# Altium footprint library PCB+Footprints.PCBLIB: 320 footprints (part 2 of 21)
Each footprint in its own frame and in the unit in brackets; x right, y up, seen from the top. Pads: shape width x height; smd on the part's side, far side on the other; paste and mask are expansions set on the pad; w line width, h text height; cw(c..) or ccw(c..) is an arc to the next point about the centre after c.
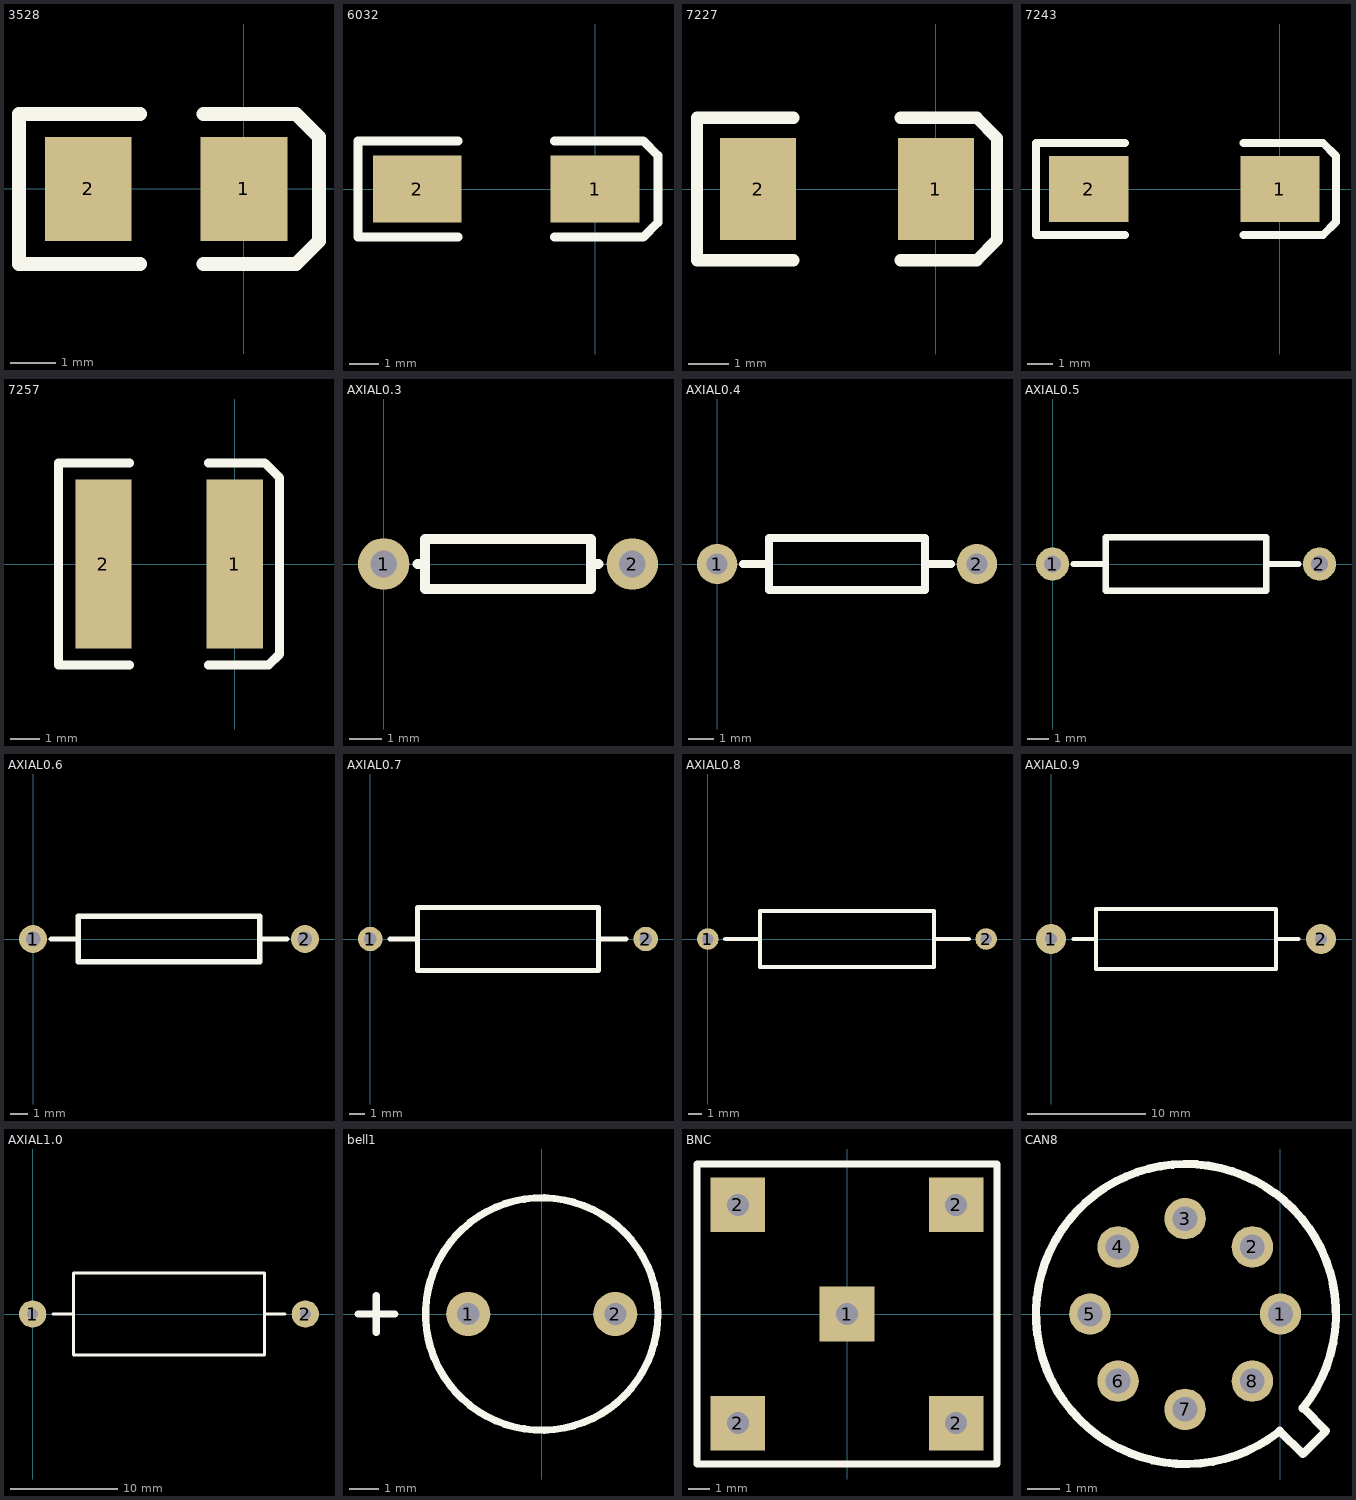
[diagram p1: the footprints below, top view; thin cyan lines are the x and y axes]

## 3528 [mil]
pads (2):
  rect 75x90 smd: 1(0,0) 2(-135,0)
TopOverlay:
  lines w12: -90,-65 -195,-65 -195,65 -90,65 ; -35,-65 45,-65 65,-45 65,45 45,65 -35,65

## 6032 [mil]
pads (2):
  rect 120x90 smd: 1(0,0) 2(-240,0)
TopOverlay:
  lines w12: -185,-65 -320,-65 -320,65 -185,65 ; -55,-65 65,-65 85,-45 85,45 65,65 -55,65

## 7227 [mil]
pads (2):
  rect 75x100 smd: 1(0,0) 2(-175,0)
TopOverlay:
  lines w12: -140,-70 -235,-70 -235,70 -140,70 ; -35,-70 40,-70 60,-50 60,50 40,70 -35,70

## 7243 [mil]
pads (2):
  rect 120x100 smd: 1(0,0) 2(-290,0)
TopOverlay:
  lines w12: -235,-70 -370,-70 -370,70 -235,70 ; -55,-70 65,-70 85,-50 85,50 65,70 -55,70

## 7257 [mil]
pads (2):
  rect 75x225 smd: 1(0,0) 2(-175,0)
TopOverlay:
  lines w12: -140,-135 -235,-135 -235,135 -140,135 ; -35,-135 45,-135 60,-120 60,115 40,135 -35,135

## AXIAL0.3 [mil]
pads (2):
  round 62 hole 32: 1(0,0) 2(300,0)
TopOverlay:
  lines w12: 41,0 50,0 ; 259,0 250,0 ; 250,0 250,-30 50,-30 50,30 250,30 250,0

## AXIAL0.4 [mil]
pads (2):
  round 62 hole 32: 1(0,0) 2(400,0)
TopOverlay:
  lines w12: 40,0 80,0 ; 320,0 360,0 ; 80,-40 80,40 320,40 320,-40 80,-40

## AXIAL0.5 [mil]
pads (2):
  round 62 hole 32: 1(0,0) 2(500,0)
TopOverlay:
  lines w12: 40,0 100,0 ; 400,0 460,0 ; 100,-50 100,50 400,50 400,-50 100,-50

## AXIAL0.6 [mil]
pads (2):
  round 62 hole 32: 1(0,0) 2(600,0)
TopOverlay:
  lines w12: 40,0 100,0 ; 500,0 560,0 ; 100,-50 100,50 500,50 500,-50 100,-50

## AXIAL0.7 [mil]
pads (2):
  round 62 hole 32: 1(0,0) 2(700,0)
TopOverlay:
  lines w12: 50,0 120,0 ; 580,0 650,0 ; 120,-80 120,80 580,80 580,-80 120,-80

## AXIAL0.8 [mil]
pads (2):
  round 62 hole 32: 1(0,0) 2(800,0)
TopOverlay:
  lines w12: 50,0 150,0 ; 650,0 750,0 ; 150,-80 150,80 650,80 650,-80 150,-80

## AXIAL0.9 [mil]
pads (2):
  round 100 hole 40: 1(0,0) 2(900,0)
TopOverlay:
  lines w12: 75,0 150,0 ; 750,0 825,0 ; 150,-100 150,100 750,100 750,-100 150,-100

## AXIAL1.0 [mil]
pads (2):
  round 100 hole 40: 1(0,0) 2(1000,0)
TopOverlay:
  lines w12: 75,0 150,0 ; 850,0 925,0 ; 150,-150 150,150 850,150 850,-150 150,-150

## bell1 [mil]
pads (2):
  round 60 hole 30: 1(-100,0) 2(100,0)
TopOverlay:
  circle w10: c0,0 r158.11
  lines w10: -250,0 -200,0 ; -225,-25 -225,25

## BNC [mil]
pads (5):
  rect 100x100 hole 40: 1(0,0) 2(-200,-200) 2(-200,200) 2(200,-200) 2(200,200)
TopOverlay:
  lines w12: -275,-275 275,-275 275,275 -275,275 -275,-275

## CAN8 [mil]
pads (8):
  round 50 hole 30: 1(0,0) 2(-34,81) 3(-115,115) 4(-196,81) 5(-230,0) 6(-196,-81) 7(-115,-115) 8(-34,-81)
TopOverlay:
  lines w10: -2.57,-142.63 cw(c-114,0) 26.66,-113.91 ; -1,-141 27,-169 55,-141 27,-113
